Omron CX-Programmer project 新工程 (CX-Programmer 9.50)

# PLC 新PLC1: CP1E NA

## Global symbols (name address type ; comment)
101.03 BOOL  ; 观察状态
C000 BOOL  ; 计数器设置值
W0.00 BOOL  ; 加计数启动
W0.01 BOOL  ; 减计数启动
W0.02 BOOL  ; 复位计数器

## Program 新程序1 (cyclic task 0)

### Section 段1

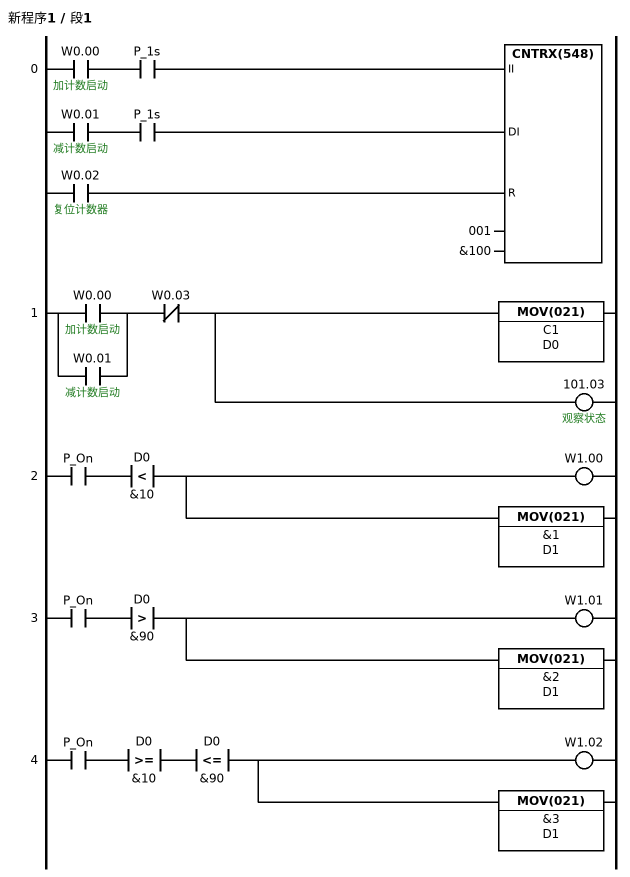
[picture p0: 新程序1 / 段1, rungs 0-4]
; rung 0
LD W0.00  ; 加计数启动
AND P_1s
LD W0.01  ; 减计数启动
AND P_1s
LD W0.02  ; 复位计数器
CNTRX(548) 001 &100
; rung 1
LD W0.00  ; 加计数启动
OR W0.01  ; 减计数启动
ANDNOT W0.03
MOV(021) C1 D0
OUT 101.03  ; 观察状态
; rung 2
LD P_On
AND<(310) D0 &10
OUT W1.00
MOV(021) &1 D1
; rung 3
LD P_On
AND>(320) D0 &90
OUT W1.01
MOV(021) &2 D1
; rung 4
LD P_On
AND>=(325) D0 &10
AND<=(315) D0 &90
OUT W1.02
MOV(021) &3 D1

### Section END
; rung 0
END(001)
